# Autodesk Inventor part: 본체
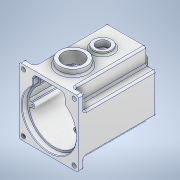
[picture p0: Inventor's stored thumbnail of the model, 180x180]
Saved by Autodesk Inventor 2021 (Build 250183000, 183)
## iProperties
Created: 2022-08
Part Number: 본체
Material: 알루미늄 6061
Document SubType Name: Modeling
Designer: Owner
Mass: 1404.24 g
Surface Area: 1170.95 cm^2
Volume: 520.089 cm^3
Density: 2.7 g/cm^3
Appearance: 알루미늄 - 평지
Author: Owner
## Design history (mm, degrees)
sketch "스케치1"
  geometry: L1 (-49, 55)-(49, 55); L2 (49, 55)-(49, -55); L3 (49, -55)-(-49, -55); L4 (-49, -55)-(-49, 55); L5 (-49, 55)-(49, -55); L6 (49, 55)-(-49, -55); 1 further point
  constraints: 12 end point, 2 midpoint, 2 parallel, 1 horizontal, 1 perpendicular
  dimensions: "d0" = 98 distance of L2.end L3.end; "d1" = 110 distance of L1.end L2.end
extrude "돌출1" new body sketch "스케치1" distance "d2" = 130; taper "d3" = 0 deg
sketch "스케치4"
  geometry: L1 (49, 55)-(-49, 55) reference; L2 (33, 55)-(49, 55); L3 (49, 55)-(49, 28); L4 (49, 28)-(33, 28); L5 (33, 28)-(33, 55); L6 (-49, -55)-(49, -55) reference; L7 (33, -38)-(49, -38); L8 (49, -38)-(49, -55); L9 (49, -55)-(33, -55); L10 (33, -55)-(33, -38); L11 (49, -55)-(49, 55) reference; 4 further points
  constraints: 16 end point, 4 parallel, 2 horizontal, 2 perpendicular, 2 point on line, 1 midpoint
  dimensions: "d9" = 16 distance of L3.end L4.end; "d10" = 16 distance of L7.start L7.end; "d11" = 27 distance of L4.end L2.start; "d12" = 17 distance of L9.end L7.start
extrude "돌출2" cut sketch "스케치4" distance "d13" = 120; taper "d14" = 0 deg
sketch "스케치5"
  geometry: L1 (-49, -55)-(49, -55) reference; L2 (-20, 48)-(20, 48); L3 (26, 42)-(26, 33.249); L4 (-26, 33.249)-(-26, 42); A1 r 45 centre (0, -5) between (-27.188, 30.859) and (27.188, 30.859); A2 r 3 centre (-29, 33.249) between (-27.188, 30.859) and (-26, 33.249); A3 r 3 centre (29, 33.249) between (26, 33.249) and (27.188, 30.859); A4 r 6 centre (-20, 42) between (-20, 48) and (-26, 42); A5 r 6 centre (20, 42) between (26, 42) and (20, 48); 5 further points
  constraints: 12 point on circle, 8 tangent, 6 end point, 6 point on line, 5 centre point, 2 equal radius, 1 horizontal, 1 parallel, 1 perpendicular, 1 vertical alignment
  dimensions: "d15" = 50 distance from line of A1.centre L1; "d16" = 45 radius of A1; "d17" = 52 distance between parallel lines of L3 L4; "d18" = 26 distance from line of A1.centre L3; "d19" = 53 distance from line of L2 A1.centre; "d20" = 3 radius of A2; "d23" = 6 radius of A4
extrude "돌출3" cut sketch "스케치5" distance "d21" = 9; taper "d22" = 0 deg
fillet "모깎기1" dims "d24" = 3
fillet "모깎기2" dims "d25" = 3
fillet "모깎기3" dims "d26" = 3
fillet "모깎기4" dims "d27" = 3
fillet "모깎기5" dims "d28" = 3
sketch "스케치6"
  geometry: L1 (-27, 33)-(27, 33); L2 (27, 33)-(27, -21); L3 (27, -21)-(-27, -21); L4 (-27, -21)-(-27, 33); L5 (-27, 33)-(27, -21); L6 (27, 33)-(-27, -21); L7 (-30, -55)-(30, -55) reference; 3 further points
  constraints: 12 end point, 4 midpoint, 2 parallel, 1 horizontal, 1 perpendicular, 1 vertical alignment
  dimensions: "d29" = 54 distance of L2.end L3.end; "d30" = 54 distance of L1.end L2.end; "d109" = 61 distance from line of point (0, 6) L7
extrude "돌출4" join sketch "스케치6" distance "d31" = 7; taper "d32" = 0 deg
fillet "모깎기6" dims "d33" = 3
fillet "모깎기7" dims "d34" = 3
sketch "스케치7"
  geometry: L1 (27, -18)-(27, 30) reference; L2 (24, 33)-(-24, 33) reference; 2 further points
  constraints: 1 coincident
  dimensions: "d110" = 27 distance from line of point (0, 6) L1; "d111" = 27 distance from line of point (0, 6) L2
hole "구멍1" sketch "스케치7" at (0, 6) diameter "d35" = 32; stored, may be unused: countersink angle "d39" = 90 deg, drill point angle "d41" = 0 deg; dims "d36" = 8, "d37" = 4, "d38" = 2, "d40" = 8.3
chamfer "모따기1" distance "d42" = 0.8; stored, may be unused: second distance "d43" = 2, angle "d44" = 30 deg
sketch "스케치8"
  geometry: L1 (92, 0)-(0, 0) reference; C1 r 15 at (46, 89); 2 further points
  constraints: 1 centre point, 1 midpoint, 1 vertical alignment
  dimensions: "d45" = 30 diameter of C1; "d46" = 89 distance from line of C1.centre L1
extrude "돌출5" join sketch "스케치8" distance "d47" = 5; taper "d48" = 0 deg
sketch "스케치9"
  geometry: L1 (92, 0)-(0, 0) reference; C1 r 22.5 at (46, 40); C2 r 15 at (46, 89) reference; 1 further point
  constraints: 1 centre point, 1 vertical alignment
  dimensions: "d49" = 45 diameter of C1; "d50" = 40 distance from line of C1.centre L1
extrude "돌출6" join sketch "스케치9" distance "d51" = 10; taper "d52" = 0 deg
fillet "모깎기8" dims "d53" = 3
sketch "스케치10"
  geometry: L1 (49, -52)-(49, 52) reference; L2 (-46, -55)-(46, -55) reference; 5 further points
  constraints: 2 horizontal alignment, 2 vertical alignment
  dimensions: "d54" = 7 distance from line of point (42, -48) L1; "d55" = 7 distance from line of point (42, -48) L2; "d56" = 96 distance of point (42, 48) point (42, -48); "d57" = 84 distance of point (-42, -48) point (42, -48)
hole "구멍2" sketch "스케치10" at (42, -48), (-42, -48), (-42, 48), (42, 48) diameter "d58" = 7; stored, may be unused: countersink angle "d62" = 90 deg, drill point angle "d64" = 0 deg; dims "d59" = 8, "d60" = 4, "d61" = 2, "d63" = 10
sketch "스케치11"
  geometry: L1 (-130, 104)-(-130, 83) reference; L2 (-13, 107)-(-127, 107) reference; 2 further points
  constraints: 1 other
  dimensions: "d65" = 65 distance from line of point (-65, 47) L1; "d66" = 60 distance from line of point (-65, 47) L2
feature "엠보싱1" sketch "스케치11" dims "d67" = 0.5, "d68" = 0
sketch "스케치13"
  geometry: C1 r 16 at (0, 0) reference; 2 further points
  constraints: 1 coincident
hole "구멍3" sketch "스케치13" at (0, 0) diameter "d71" = 28; stored, may be unused: countersink angle "d75" = 90 deg, drill point angle "d77" = 0 deg; dims "d72" = 8, "d73" = 4, "d74" = 2, "d76" = 10
fillet "모깎기9" dims "d78" = 0.3
sketch "스케치14"
  geometry: L1 (-20, 48)-(20, 48) reference; L2 (-26, 33.249)-(-26, 42) reference; L3 (26, 42)-(26, 33.249) reference; L4 (-23, 33.249)-(-23, 42); L5 (-20, 45)-(20, 45); L6 (23, 42)-(23, 33.249); L7 (-70.297, -5)-(83.266, -5); L8 (-46, -55)-(46, -55) reference; L9 (35.777, -1)-(41.809, -1); L10 (-41.809, -1)-(-35.777, -1); L11 (-41.809, -9)-(-35.777, -9); L12 (35.777, -9)-(41.809, -9); C1 r 14 at (0, 6) reference; A1 r 6 centre (-20, 42) between (-20, 48) and (-26, 42) reference; A2 r 3 centre (-29, 33.249) between (-27.188, 30.859) and (-26, 33.249) reference; A3 r 45 centre (0, -5) between (-27.188, 30.859) and (27.188, 30.859) reference; A4 r 3 centre (29, 33.249) between (26, 33.249) and (27.188, 30.859) reference; A5 r 6 centre (20, 42) between (26, 42) and (20, 48) reference; A6 r 6 centre (-29, 33.249) between (-25.375, 28.468) and (-23, 33.249); A7 r 3 centre (-20, 42) between (-20, 45) and (-23, 42); A8 r 3 centre (20, 42) between (23, 42) and (20, 45); A9 r 6 centre (29, 33.249) between (23, 33.249) and (25.375, 28.468); A10 r 36 centre (0, -5) between (-36, -5) and (36, -5); A11 r 4 centre (-36, -5) between (-36, -9) and (-36, -1); A12 r 4 centre (36, -5) between (36, -1) and (36, -9); A13 r 42 centre (0, -5) between (-25.375, 28.468) and (-41.809, -1); A14 r 42 centre (0, -5) between (-41.809, -9) and (41.809, -9); A15 r 42 centre (0, -5) between (41.809, -1) and (25.375, 28.468); 1 further point
  constraints: 24 point on circle, 16 end point, 10 centre point, 6 point on line, 5 horizontal, 4 tangent, 1 coincident, 6 other
  dimensions: "d89" = 50 distance between parallel lines of L7 L8; "d90" = 72 diameter of A10; "d91" = 8 diameter of A11; "d92" = 8 diameter of A12; "d93" = 42 radius of A15; "d94" = 42 radius of A14; "d95" = 42 radius of A13; "d96" = 6 radius of A6
extrude "돌출7" cut sketch "스케치14" distance "d80" = 112; taper "d81" = 0 deg
fillet "모깎기10" dims "d97" = 3
fillet "모깎기11" dims "d98" = 3
chamfer "모따기2" distance "d99" = 1; stored, may be unused: second distance "d100" = 2, angle "d101" = 30 deg
sketch "스케치16"
  geometry: A1 r 4 centre (-36, -5) between (-36, -9) and (-36, -1) reference; A2 r 4 centre (36, -5) between (36, -1) and (36, -9) reference; 3 further points
  constraints: 2 coincident
hole "구멍5" sketch "스케치16" at (-36, -5), (36, -5) diameter "d102" = 3.242; stored, may be unused: countersink angle "d106" = 90 deg, drill point angle "d108" = 118 deg; dims "d103" = 7, "d104" = 4, "d105" = 2, "d107" = 9
sketch "스케치17"
  geometry: C1 r 15 at (23, -80) reference; 1 further point
hole "구멍6" sketch "스케치17" at (23, -80) diameter "d112" = 20; stored, may be unused: countersink angle "d116" = 90 deg, drill point angle "d118" = 0 deg; dims "d113" = 7, "d114" = 30, "d115" = 5, "d117" = 20
sketch "스케치18"
  geometry: C1 r 22.5 at (0, 0) reference; 2 further points
  constraints: 1 coincident
hole "구멍7" sketch "스케치18" at (0, 0) diameter "d119" = 33.376; stored, may be unused: countersink angle "d123" = 90 deg, drill point angle "d125" = 0 deg; dims "d120" = 70, "d121" = 30, "d122" = 5, "d124" = 77.3
sketch "스케치19"
  geometry: L1 (-46, -55)-(46, -55) reference; C1 r 17.5 at (0, 6); C2 r 11 at (0, -25); A1 r 21 centre (0, 6) between (8.978, -12.984) and (-8.978, -12.984); A2 r 15 centre (0, -25) between (-8.978, -12.984) and (8.978, -12.984); 1 further point
  constraints: 4 centre point, 4 point on circle, 3 vertical alignment, 2 coincident
  dimensions: "d126" = 61 distance from line of A1.centre L1; "d127" = 42 diameter of A1; "d128" = 30 diameter of A2; "d129" = 35 diameter of C1; "d130" = 22 diameter of C2; "d131" = 31 distance of A2.centre A1.centre
extrude "돌출8" join sketch "스케치19" distance "d132" = 7; taper "d133" = 0 deg
sketch "스케치20"
  geometry: C1 r 11 at (0, 0) reference; 2 further points
  constraints: 1 coincident
hole "구멍8" sketch "스케치20" at (0, 0) diameter "d134" = 19; stored, may be unused: countersink angle "d138" = 90 deg, drill point angle "d140" = 0 deg; dims "d135" = 70, "d136" = 30, "d137" = 5, "d139" = 3
fillet "모깎기12" dims "d141" = 3
fillet "모깎기13" dims "d142" = 3
chamfer "모따기3" distance "d143" = 1; stored, may be unused: second distance "d144" = 2, angle "d145" = 30 deg
fillet "모깎기14" dims "d146" = 3
sketch "스케치21"
  geometry: C1 r 18.5 at (0, 0) reference; 2 further points
  constraints: 1 coincident
hole "구멍9" sketch "스케치21" at (0, 0) diameter "d147" = 35; stored, may be unused: countersink angle "d151" = 90 deg, drill point angle "d153" = 0 deg; dims "d148" = 70, "d149" = 30, "d150" = 5, "d152" = 3
chamfer "모따기4" distance "d154" = 1; stored, may be unused: second distance "d155" = 2, angle "d156" = 30 deg
fillet "모깎기17" dims "d159" = 0.3
node "솔리드1"
mirror "미러1"
node "투영된 루프1"
node "투영된 루프2"
feature "A9D066F2-1C7D-4E18-AEED-F7BC21143FA4" dims "d35" = 32, "d36" = 8, "d37" = 4, "d38" = 2, "d39" = 90 deg, "d40" = 8.3, "d41" = 0
other parameters: "d79" = 3
